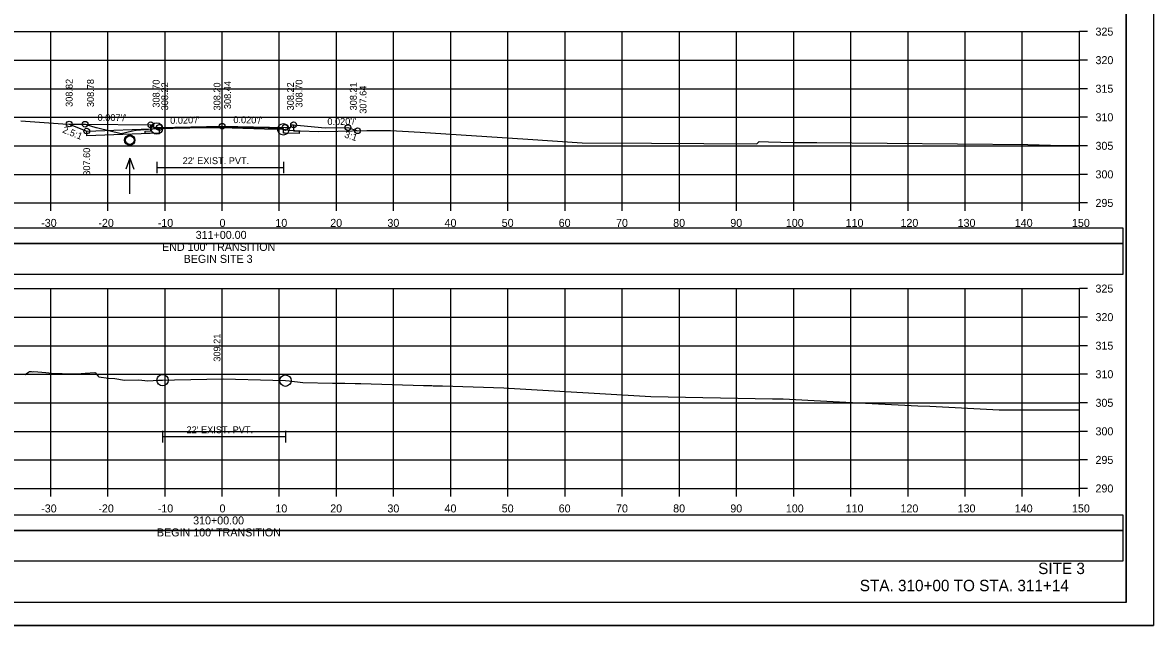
# Model space of a CAD drawing. Extents: x 1370538 to 1372872, y 376220 to 381127.
# Drawn here: x 1370673.7 to 1370871.5, y 378064.2 to 378169.8 of the extents above; entities that cross this region are included whole.
import ezdxf

# ---------------------------------------------------------------- set-up
doc = ezdxf.new("R2010")
doc.units = 0
for name, color, linetype in [('R_Border', 7, 'Continuous'), ('R_Border Notes', 7, 'Continuous'), ('R_Border PE', 7, 'Continuous'), ('R_Border Prem', 7, 'Continuous'), ('R_Dimension', 7, 'Continuous'), ('R_Fin Surface', 7, 'Continuous'), ('R_Grid', 7, 'Continuous'), ('R_Horz Alg Annot', 7, 'Continuous'), ('R_No Plot', 7, 'Continuous'), ('R_Proposed Road', 7, 'Continuous'), ('R_Water', 7, 'Continuous'), ('R_Water Annot', 7, 'Continuous'), ('R_Xsect Elev', 7, 'Continuous'), ('R_Xsect Slope', 7, 'Continuous')]:
    doc.layers.add(name, color=color, linetype=linetype)

msp = doc.modelspace()

# ---------------------------------------------------------------- linework, layer by layer
at = {"layer": 'R_Border'}
for p, q in [((1370697.18, 378145.38), (1370697.18, 378143.38)), ((1370719.32, 378145.38), (1370719.32, 378143.38)), ((1370697.18, 378144.38), (1370719.32, 378144.38)), ((1370698.19, 378098.26), (1370698.19, 378096.26)), ((1370719.68, 378098.26), (1370719.68, 378096.26)), ((1370698.19, 378097.26), (1370719.68, 378097.26))]:
    msp.add_line(p, q, dxfattribs=at)
for points in [[(1370708.61, 378151.45), (1370697.61, 378151.23), (1370697.61, 378150.4), (1370697.61, 378150.4), (1370695.11, 378150.35), (1370695.11, 378150.77), (1370696.11, 378150.79), (1370696.11, 378151.88)], [(1370721.11, 378151.88), (1370721.11, 378150.79), (1370722.11, 378150.77), (1370722.11, 378150.35), (1370719.61, 378150.4), (1370719.32, 378150.41), (1370719.32, 378151.24), (1370708.61, 378151.45)]]:
    msp.add_lwpolyline(points, dxfattribs=at)
at = {"layer": 'R_Border Notes'}
for q in [(1370866.79, 378273.65), (1370550.61, 378068.19)]:
    msp.add_line((1370866.79, 378068.19), q, dxfattribs=at)
at = {"layer": 'R_Border Prem'}
for p, q in [((1370858.61, 378138.19), (1370858.61, 378168.19)), ((1370860.01, 378168.19), (1370858.61, 378168.19)), ((1370860.01, 378163.19), (1370858.61, 378163.19)), ((1370860.01, 378158.19), (1370858.61, 378158.19)), ((1370860.01, 378153.19), (1370858.61, 378153.19)), ((1370860.01, 378148.19), (1370858.61, 378148.19)), ((1370860.01, 378143.19), (1370858.61, 378143.19)), ((1370558.61, 378138.19), (1370858.61, 378138.19)), ((1370678.61, 378136.79), (1370678.61, 378138.19)), ((1370688.61, 378136.79), (1370688.61, 378138.19)), ((1370698.61, 378136.79), (1370698.61, 378138.19)), ((1370708.61, 378136.79), (1370708.61, 378138.19)), ((1370718.61, 378136.79), (1370718.61, 378138.19)), ((1370728.61, 378136.79), (1370728.61, 378138.19)), ((1370738.61, 378136.79), (1370738.61, 378138.19)), ((1370748.61, 378136.79), (1370748.61, 378138.19)), ((1370758.61, 378136.79), (1370758.61, 378138.19)), ((1370768.61, 378136.79), (1370768.61, 378138.19)), ((1370778.61, 378136.79), (1370778.61, 378138.19)), ((1370788.61, 378136.79), (1370788.61, 378138.19)), ((1370798.61, 378136.79), (1370798.61, 378138.19)), ((1370808.61, 378136.79), (1370808.61, 378138.19)), ((1370818.61, 378136.79), (1370818.61, 378138.19)), ((1370828.61, 378136.79), (1370828.61, 378138.19)), ((1370838.61, 378136.79), (1370838.61, 378138.19)), ((1370848.61, 378136.79), (1370848.61, 378138.19)), ((1370858.61, 378136.79), (1370858.61, 378138.19)), ((1370860.01, 378138.19), (1370858.61, 378138.19)), ((1370858.61, 378088.19), (1370858.61, 378123.19)), ((1370860.01, 378123.19), (1370858.61, 378123.19)), ((1370860.01, 378118.19), (1370858.61, 378118.19)), ((1370860.01, 378113.19), (1370858.61, 378113.19)), ((1370860.01, 378108.19), (1370858.61, 378108.19)), ((1370860.01, 378103.19), (1370858.61, 378103.19)), ((1370860.01, 378098.19), (1370858.61, 378098.19)), ((1370860.01, 378093.19), (1370858.61, 378093.19)), ((1370558.61, 378088.19), (1370858.61, 378088.19)), ((1370678.61, 378086.79), (1370678.61, 378088.19)), ((1370688.61, 378086.79), (1370688.61, 378088.19)), ((1370698.61, 378086.79), (1370698.61, 378088.19)), ((1370708.61, 378086.79), (1370708.61, 378088.19)), ((1370718.61, 378086.79), (1370718.61, 378088.19)), ((1370728.61, 378086.79), (1370728.61, 378088.19)), ((1370738.61, 378086.79), (1370738.61, 378088.19)), ((1370748.61, 378086.79), (1370748.61, 378088.19)), ((1370758.61, 378086.79), (1370758.61, 378088.19)), ((1370768.61, 378086.79), (1370768.61, 378088.19)), ((1370778.61, 378086.79), (1370778.61, 378088.19)), ((1370788.61, 378086.79), (1370788.61, 378088.19)), ((1370798.61, 378086.79), (1370798.61, 378088.19)), ((1370808.61, 378086.79), (1370808.61, 378088.19)), ((1370818.61, 378086.79), (1370818.61, 378088.19)), ((1370828.61, 378086.79), (1370828.61, 378088.19)), ((1370838.61, 378086.79), (1370838.61, 378088.19)), ((1370848.61, 378086.79), (1370848.61, 378088.19)), ((1370858.61, 378086.79), (1370858.61, 378088.19)), ((1370860.01, 378088.19), (1370858.61, 378088.19))]:
    msp.add_line(p, q, dxfattribs=at)
at = {"layer": 'R_Dimension'}
for points in [[(1370673.36, 378152.58), (1370680.76, 378152.03), (1370682.47, 378152), (1370684.63, 378151.97), (1370686.53, 378151.41), (1370686.65, 378151.39), (1370686.87, 378151.32), (1370690.92, 378150.34), (1370692.95, 378150.81), (1370693.57, 378150.95), (1370694.34, 378151), (1370697.18, 378151.23), (1370702.94, 378151.31), (1370708.46, 378151.39), (1370716, 378151.16), (1370719.32, 378151.08), (1370720.42, 378150.92), (1370722.26, 378150.84), (1370725.44, 378150.71), (1370728.83, 378150.76), (1370733.95, 378150.85), (1370736.21, 378150.87), (1370737.78, 378150.86), (1370737.9, 378150.86), (1370738.07, 378150.89), (1370740.18, 378150.76), (1370743.27, 378150.56), (1370762.07, 378149.36), (1370771.61, 378148.73), (1370783.73, 378148.67), (1370802.06, 378148.53), (1370802.19, 378148.61), (1370802.58, 378148.93), (1370804.17, 378148.87), (1370808.54, 378148.79), (1370812.17, 378148.79), (1370812.27, 378148.79), (1370812.66, 378148.78), (1370849.57, 378148.42), (1370853.55, 378148.3), (1370858.61, 378148.27)], [(1370672.94, 378108.18), (1370674.16, 378108.14), (1370674.75, 378108.56), (1370674.93, 378108.69), (1370675.17, 378108.68), (1370675.35, 378108.63), (1370675.64, 378108.65), (1370677.76, 378108.47), (1370679.25, 378108.31), (1370680.63, 378108.29), (1370682.08, 378108.28), (1370683.25, 378108.26), (1370684.67, 378108.35), (1370686.34, 378108.47), (1370686.47, 378108.47), (1370686.54, 378108.27), (1370686.9, 378107.84), (1370687.01, 378107.74), (1370688.74, 378107.52), (1370689.84, 378107.42), (1370691.5, 378107.17), (1370694.03, 378107.18), (1370695.6, 378107.04), (1370697.48, 378107.17), (1370698.19, 378107.16), (1370700.27, 378107.2), (1370708.81, 378107.4), (1370717.47, 378107.15), (1370719.68, 378107.07), (1370720.34, 378107.01), (1370722.72, 378106.74), (1370727.94, 378106.64), (1370728.79, 378106.63), (1370730.1, 378106.62), (1370731.91, 378106.59), (1370732.5, 378106.59), (1370732.86, 378106.54), (1370743.86, 378106.2), (1370745.28, 378106.19), (1370745.53, 378106.18), (1370747.14, 378106.13), (1370757.9, 378105.79), (1370758.51, 378105.77), (1370758.78, 378105.76), (1370783.59, 378104.29), (1370804.89, 378103.91), (1370806.54, 378103.9), (1370806.76, 378103.9), (1370812.21, 378103.61), (1370816.64, 378103.37), (1370817.73, 378103.32), (1370830.35, 378102.66), (1370832.44, 378102.58), (1370844.53, 378101.96), (1370846.52, 378101.95), (1370858.61, 378101.94)]]:
    msp.add_lwpolyline(points, dxfattribs=at)
at = {"layer": 'R_Fin Surface'}
for points in [[(1370684.63, 378151.97), (1370696.11, 378151.88), (1370696.61, 378151.88), (1370696.61, 378151.38), (1370697.61, 378151.4), (1370708.61, 378151.62)], [(1370708.61, 378151.62), (1370719.61, 378151.4), (1370720.61, 378151.38), (1370720.61, 378151.88), (1370721.11, 378151.88), (1370726.61, 378151.31), (1370730.61, 378151.39), (1370732.31, 378150.82)]]:
    msp.add_lwpolyline(points, dxfattribs=at)
at = {"layer": 'R_Grid'}
for p, q in [((1370558.61, 378168.19), (1370858.61, 378168.19)), ((1370678.61, 378138.19), (1370678.61, 378168.19)), ((1370688.61, 378138.19), (1370688.61, 378168.19)), ((1370698.61, 378138.19), (1370698.61, 378168.19)), ((1370708.61, 378138.19), (1370708.61, 378168.19)), ((1370718.61, 378138.19), (1370718.61, 378168.19)), ((1370728.61, 378138.19), (1370728.61, 378168.19)), ((1370738.61, 378138.19), (1370738.61, 378168.19)), ((1370748.61, 378138.19), (1370748.61, 378168.19)), ((1370758.61, 378138.19), (1370758.61, 378168.19)), ((1370768.61, 378138.19), (1370768.61, 378168.19)), ((1370778.61, 378138.19), (1370778.61, 378168.19)), ((1370788.61, 378138.19), (1370788.61, 378168.19)), ((1370798.61, 378138.19), (1370798.61, 378168.19)), ((1370808.61, 378138.19), (1370808.61, 378168.19)), ((1370818.61, 378138.19), (1370818.61, 378168.19)), ((1370828.61, 378138.19), (1370828.61, 378168.19)), ((1370838.61, 378138.19), (1370838.61, 378168.19)), ((1370848.61, 378138.19), (1370848.61, 378168.19)), ((1370858.61, 378138.19), (1370858.61, 378168.19)), ((1370558.61, 378163.19), (1370858.61, 378163.19)), ((1370558.61, 378158.19), (1370858.61, 378158.19)), ((1370558.61, 378153.19), (1370858.61, 378153.19)), ((1370558.61, 378148.19), (1370858.61, 378148.19)), ((1370558.61, 378143.19), (1370858.61, 378143.19)), ((1370558.61, 378138.19), (1370858.61, 378138.19)), ((1370558.61, 378123.19), (1370858.61, 378123.19)), ((1370678.61, 378088.19), (1370678.61, 378123.19)), ((1370688.61, 378088.19), (1370688.61, 378123.19)), ((1370698.61, 378088.19), (1370698.61, 378123.19)), ((1370708.61, 378088.19), (1370708.61, 378123.19)), ((1370718.61, 378088.19), (1370718.61, 378123.19)), ((1370728.61, 378088.19), (1370728.61, 378123.19)), ((1370738.61, 378088.19), (1370738.61, 378123.19)), ((1370748.61, 378088.19), (1370748.61, 378123.19)), ((1370758.61, 378088.19), (1370758.61, 378123.19)), ((1370768.61, 378088.19), (1370768.61, 378123.19)), ((1370778.61, 378088.19), (1370778.61, 378123.19)), ((1370788.61, 378088.19), (1370788.61, 378123.19)), ((1370798.61, 378088.19), (1370798.61, 378123.19)), ((1370808.61, 378088.19), (1370808.61, 378123.19)), ((1370818.61, 378088.19), (1370818.61, 378123.19)), ((1370828.61, 378088.19), (1370828.61, 378123.19)), ((1370838.61, 378088.19), (1370838.61, 378123.19)), ((1370848.61, 378088.19), (1370848.61, 378123.19)), ((1370858.61, 378088.19), (1370858.61, 378123.19)), ((1370558.61, 378118.19), (1370858.61, 378118.19)), ((1370558.61, 378113.19), (1370858.61, 378113.19)), ((1370558.61, 378108.19), (1370858.61, 378108.19)), ((1370558.61, 378103.19), (1370858.61, 378103.19)), ((1370558.61, 378098.19), (1370858.61, 378098.19)), ((1370558.61, 378093.19), (1370858.61, 378093.19)), ((1370558.61, 378088.19), (1370858.61, 378088.19))]:
    msp.add_line(p, q, dxfattribs=at)
at = {"layer": 'R_Horz Alg Annot'}
for points in [[(1370681.84, 378152.01), (1370684.91, 378150.78), (1370697.61, 378151.23)], [(1370697.61, 378151.23), (1370697.61, 378150.4), (1370684.91, 378149.95), (1370684.91, 378150.78)]]:
    msp.add_lwpolyline(points, dxfattribs=at)
for points in [[(1370551.13, 378131.06), (1370866.25, 378131.06), (1370866.25, 378133.77), (1370551.13, 378133.77)], [(1370551.13, 378125.74), (1370866.25, 378125.74), (1370866.25, 378131.06), (1370551.13, 378131.06)], [(1370551.13, 378080.81), (1370866.25, 378080.81), (1370866.25, 378083.52), (1370551.13, 378083.52)], [(1370551.13, 378075.49), (1370866.25, 378075.49), (1370866.25, 378080.81), (1370551.13, 378080.81)]]:
    msp.add_lwpolyline(points, close=True, dxfattribs=at)
at = {"layer": 'R_No Plot'}
msp.add_line((1370538.21, 378064.21), (1370871.54, 378064.21), dxfattribs=at)
for points in [[(1370538.2, 378277.54), (1370871.54, 378277.54), (1370871.54, 378064.2), (1370538.2, 378064.2)], [(1370784.53, 378273.65), (1370784.53, 378263.77), (1370820.26, 378263.77), (1370820.26, 378260.85), (1370843.46, 378260.85), (1370843.46, 378236.52), (1370866.79, 378236.52), (1370866.79, 378068.19), (1370550.61, 378068.19), (1370550.61, 378273.65)]]:
    msp.add_lwpolyline(points, close=True, dxfattribs=at)
for centre, radius in [((1370681.84, 378152.01), 0.5), ((1370684.63, 378151.97), 0.5), ((1370684.63, 378151.97), 0.5), ((1370684.91, 378150.78), 0.5), ((1370696.11, 378151.88), 0.5), ((1370697.18, 378151.23), 1), ((1370697.61, 378151.4), 0.5), ((1370708.61, 378151.62), 0.5), ((1370708.61, 378151.62), 0.5), ((1370719.32, 378151.08), 1), ((1370719.61, 378151.4), 0.5), ((1370721.11, 378151.88), 0.5), ((1370730.61, 378151.39), 0.5), ((1370732.31, 378150.82), 0.5), ((1370692.44, 378149.18), 0.917), ((1370698.19, 378107.16), 1), ((1370719.68, 378107.07), 1)]:
    msp.add_circle(centre, radius, dxfattribs=at)
at = {"layer": 'R_Water'}
msp.add_circle((1370692.44, 378149.18), 0.75, dxfattribs=at)
at = {"layer": 'R_Water Annot'}
for p, q in [((1370692.44, 378146.04), (1370691.74, 378144.12)), ((1370692.44, 378139.76), (1370692.44, 378146.04)), ((1370692.44, 378146.04), (1370693.14, 378144.12))]:
    msp.add_line(p, q, dxfattribs=at)
at = {"layer": 'R_Xsect Elev'}
for p, q in [((1370708.61, 378151.38), (1370708.61, 378161.38)), ((1370708.61, 378107.39), (1370708.61, 378117.39))]:
    msp.add_line(p, q, dxfattribs=at)

# ---------------------------------------------------------------- texts
at = {"layer": 'R_Border PE'}
for s, p in [('325', (1370861.41, 378167.49)), ('320', (1370861.41, 378162.49)), ('315', (1370861.41, 378157.49)), ('310', (1370861.41, 378152.49)), ('305', (1370861.41, 378147.49)), ('300', (1370861.41, 378142.49)), ('295', (1370861.41, 378137.49)), ('-30', (1370676.95, 378133.99)), ('-20', (1370686.95, 378133.99)), ('-10', (1370697.34, 378133.99)), ('0', (1370708.15, 378133.99)), ('10', (1370717.92, 378133.99)), ('20', (1370727.52, 378133.99)), ('30', (1370737.52, 378133.99)), ('40', (1370747.52, 378133.99)), ('50', (1370757.52, 378133.99)), ('60', (1370767.49, 378133.99)), ('70', (1370777.52, 378133.99)), ('80', (1370787.52, 378133.99)), ('90', (1370797.52, 378133.99)), ('100', (1370807.23, 378133.99)), ('110', (1370817.69, 378133.99)), ('120', (1370827.29, 378133.99)), ('130', (1370837.29, 378133.99)), ('140', (1370847.29, 378133.99)), ('150', (1370857.29, 378133.99)), ('311+00.00', (1370703.98, 378131.89)), ("END 100' TRANSITION", (1370698.1, 378129.79)), ('BEGIN SITE 3', (1370701.87, 378127.69)), ('325', (1370861.41, 378122.49)), ('320', (1370861.41, 378117.49)), ('315', (1370861.41, 378112.49)), ('310', (1370861.41, 378107.49)), ('305', (1370861.41, 378102.49)), ('300', (1370861.41, 378097.49)), ('295', (1370861.41, 378092.49)), ('290', (1370861.41, 378087.49)), ('-30', (1370676.95, 378083.99)), ('-20', (1370686.95, 378083.99)), ('-10', (1370697.34, 378083.99)), ('0', (1370708.15, 378083.99)), ('10', (1370717.92, 378083.99)), ('20', (1370727.52, 378083.99)), ('30', (1370737.52, 378083.99)), ('40', (1370747.52, 378083.99)), ('50', (1370757.52, 378083.99)), ('60', (1370767.49, 378083.99)), ('70', (1370777.52, 378083.99)), ('80', (1370787.52, 378083.99)), ('90', (1370797.52, 378083.99)), ('100', (1370807.23, 378083.99)), ('110', (1370817.69, 378083.99)), ('120', (1370827.29, 378083.99)), ('130', (1370837.29, 378083.99)), ('140', (1370847.29, 378083.99)), ('150', (1370857.29, 378083.99)), ('310+00.00', (1370703.53, 378081.89)), ("BEGIN 100' TRANSITION", (1370697.2, 378079.79))]:
    msp.add_text(s, height=1.4, dxfattribs=at).set_placement(p)
at = {"layer": 'R_Proposed Road'}
for s, p in [('SITE 3', (1370851.38, 378073.19)), ('STA. 310+00 TO STA. 311+14', (1370820.17, 378070.19))]:
    msp.add_text(s, height=2, dxfattribs=at).set_placement(p)
at = {"layer": 'R_Water'}
for p in [(1370701.7, 378144.98), (1370702.38, 378097.86)]:
    msp.add_text("22' EXIST. PVT.", height=1.2, dxfattribs=at).set_placement(p)
at = {"layer": 'R_Xsect Elev'}
for s, p in [('308.82', (1370682.44, 378155.01)), ('308.78', (1370686.18, 378154.97)), ('308.78', (1370686.18, 378154.97)), ('308.70', (1370697.66, 378154.88)), ('308.22', (1370699.16, 378154.4)), ('308.20', (1370708.31, 378154.38)), ('308.44', (1370710.16, 378154.62)), ('308.44', (1370710.16, 378154.62)), ('308.22', (1370721.16, 378154.4)), ('308.70', (1370722.66, 378154.88)), ('308.21', (1370732.16, 378154.39)), ('307.64', (1370733.86, 378153.82)), ('307.60', (1370685.51, 378142.95)), ('309.21', (1370708.31, 378110.39))]:
    msp.add_text(s, height=1.2, rotation=90, dxfattribs=at).set_placement(p)
at = {"layer": 'R_Xsect Slope'}
for s, rotation, p in [("0.007'/'", 359.5851, (1370686.81, 378152.55)), ("0.020'/'", 1.1458, (1370699.53, 378152.04)), ("0.020'/'", 358.8542, (1370710.56, 378152.18)), ("0.020'/'", 1.1458, (1370727.03, 378151.81)), ('2.5:1', 338.1986, (1370680.56, 378150.55)), ('3:1', 341.5651, (1370729.9, 378149.69))]:
    msp.add_text(s, height=1.2, rotation=rotation, dxfattribs=at).set_placement(p)

doc.saveas('drawing.dxf')
